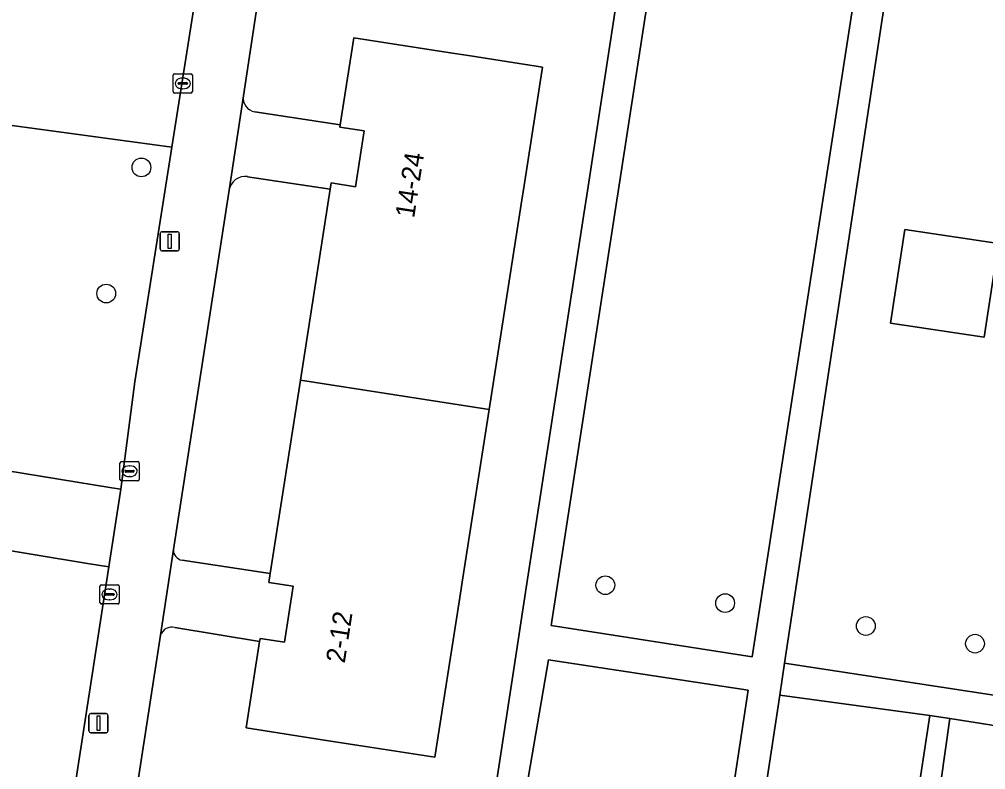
# Model space of a CAD drawing. Extents: x 161084 to 161928, y 385354 to 386522.
# Drawn here: x 161669.4 to 161719.8, y 385565.9 to 385605.1 of the extents above; entities that cross this region are included whole.
import ezdxf

# ---------------------------------------------------------------- set-up
doc = ezdxf.new("R2010")
doc.units = 0
for name, color, linetype in [('IMGEO_Boom', 7, 'Continuous'), ('IMGEO_Groenvoorziening', 7, 'Continuous'), ('IMGEO_Kolk', 7, 'Continuous'), ('IMGEO_Lichtmast', 7, 'Continuous'), ('IMGEO_Pand', 7, 'Continuous'), ('IMGEO_Pand_nummerreeks', 7, 'Continuous'), ('IMGEO_Voetpad_open', 7, 'Continuous')]:
    doc.layers.add(name, color=color, linetype=linetype)

msp = doc.modelspace()

# ---------------------------------------------------------------- linework, layer by layer
at = {"layer": 'IMGEO_Boom'}
for centre in [(161675.742, 385597.336), (161673.907, 385590.754), (161699.947, 385575.533), (161706.197, 385574.595), (161713.538, 385573.402), (161719.234, 385572.48)]:
    msp.add_circle(centre, 0.489, dxfattribs=at)
at = {"layer": 'IMGEO_Groenvoorziening'}
for points in [[(161657.824, 385601.039), (161677.325, 385598.393), (161682.306, 385629.936)], [(161682.526, 385610.747), (161681.062, 385601.073)], [(161702.191, 385606.341), (161697.119, 385573.437), (161707.611, 385571.788), (161713.072, 385607.113), (161704.883, 385608.326)], [(161676.732, 385572.916), (161675.558, 385565.255), (161684.945, 385563.794), (161686.427, 385563.563), (161693.826, 385562.411), (161695.311, 385572.063), (161695.631, 385574.145), (161695.859, 385575.628), (161698.823, 385594.901), (161698.975, 385595.889), (161700.619, 385606.575)], [(161736.552, 385603.449), (161714.658, 385606.809), (161709.299, 385571.47), (161731.363, 385568.084)], [(161681.664, 385600.231), (161686.113, 385599.559), (161686.821, 385604.108), (161691.753, 385603.34), (161692.904, 385603.16), (161696.666, 385602.574), (161695.704, 385596.399), (161695.55, 385595.411), (161693.882, 385584.702), (161692.549, 385576.144), (161692.318, 385574.661), (161691.055, 385566.552), (161686.982, 385567.187), (161685.5, 385567.417), (161681.209, 385568.086), (161681.91, 385572.586)], [(161677.325, 385598.393), (161657.824, 385601.039)], [(161663.121, 385582.422), (161674.204, 385580.619), (161674.661, 385580.545), (161675.404, 385586.149), (161677.325, 385598.393)], [(161684.036, 385586.235), (161685.589, 385596.2), (161681.285, 385596.854)], [(161680.318, 385596.144), (161677.419, 385577.388)], [(161677.87, 385576.84), (161682.463, 385576.139), (161684.036, 385586.235)], [(161674.034, 385576.484), (161672.926, 385576.668), (161664.507, 385578.062)], [(161662.849, 385544.418), (161663.304, 385544.268), (161668.139, 385543.516), (161668.928, 385543.394), (161672.366, 385565.674), (161674.034, 385576.484)], [(161681.91, 385572.586), (161677.493, 385573.331)], [(161727.809, 385567.017), (161717.914, 385568.577), (161717.223, 385563.649), (161721.705, 385562.959)]]:
    msp.add_lwpolyline(points, dxfattribs=at)
for points in [[(161719.717, 385588.484), (161720.467, 385593.373), (161715.569, 385594.099), (161714.819, 385589.209)], [(161719.717, 385588.484), (161714.819, 385589.209), (161715.569, 385594.099), (161720.467, 385593.373)], [(161707.395, 385570.046), (161696.989, 385571.64), (161695.367, 385562.217), (161705.954, 385560.553)], [(161708.692, 385535.916), (161707.425, 385536.11), (161709.051, 385546.696), (161710.63, 385556.976), (161711.897, 385556.782), (161712.382, 385559.945), (161711.116, 385560.139), (161711.784, 385564.487), (161716.127, 385563.818), (161716.872, 385568.738), (161709.056, 385569.786), (161707.615, 385560.292), (161711.058, 385559.763), (161710.876, 385558.577), (161707.433, 385559.106), (161707.374, 385558.705), (161702.137, 385524.559), (161705.558, 385523.963), (161706.317, 385528.904), (161706.975, 385533.185), (161708.242, 385532.991)]]:
    msp.add_lwpolyline(points, close=True, dxfattribs=at)
for centre, radius, start, end in [((161681.802, 385600.966), 0.748, 171.7862, 259.3406), ((161681.158, 385596.014), 0.85, 81.3757, 171.1987), ((161677.926, 385577.345), 0.508, 175.1802, 263.728), ((161677.344, 385572.699), 0.649, 76.7282, 160.4822)]:
    msp.add_arc(centre, radius, start, end, dxfattribs=at)
at = {"layer": 'IMGEO_Kolk'}
for p, q in [((161677.4, 385601.294), (161677.4, 385602.146)), ((161677.475, 385602.22), (161678.327, 385602.22)), ((161677.888, 385602), (161677.913, 385602)), ((161678.401, 385602.146), (161678.401, 385601.294)), ((161677.659, 385601.714), (161677.659, 385601.726)), ((161678.097, 385601.677), (161677.699, 385601.677)), ((161677.702, 385601.763), (161678.1, 385601.763)), ((161677.911, 385601.44), (161677.886, 385601.44)), ((161678.143, 385601.726), (161678.143, 385601.714)), ((161678.327, 385601.22), (161677.475, 385601.22)), ((161674.623, 385581.055), (161674.623, 385581.907)), ((161674.698, 385581.981), (161675.55, 385581.981)), ((161675.111, 385581.761), (161675.136, 385581.761)), ((161675.624, 385581.907), (161675.624, 385581.055)), ((161674.882, 385581.475), (161674.882, 385581.487)), ((161675.32, 385581.438), (161674.922, 385581.438)), ((161674.925, 385581.524), (161675.323, 385581.524)), ((161675.134, 385581.201), (161675.109, 385581.201)), ((161675.366, 385581.487), (161675.366, 385581.475)), ((161675.55, 385580.981), (161674.698, 385580.981)), ((161673.579, 385574.625), (161673.579, 385575.477)), ((161673.654, 385575.551), (161674.506, 385575.551)), ((161673.838, 385575.045), (161673.838, 385575.057)), ((161673.881, 385575.094), (161674.279, 385575.094)), ((161674.067, 385575.331), (161674.092, 385575.331)), ((161674.322, 385575.057), (161674.322, 385575.045)), ((161674.58, 385575.477), (161674.58, 385574.625)), ((161674.506, 385574.551), (161673.654, 385574.551)), ((161674.276, 385575.008), (161673.878, 385575.008)), ((161674.09, 385574.771), (161674.065, 385574.771))]:
    msp.add_line(p, q, dxfattribs=at)
for points in [[(161677.4, 385601.294), (161677.4, 385602.146)], [(161677.475, 385602.22), (161678.327, 385602.22)], [(161678.401, 385602.146), (161678.401, 385601.294)], [(161678.327, 385601.22), (161677.475, 385601.22)], [(161674.623, 385581.055), (161674.623, 385581.907)], [(161674.698, 385581.981), (161675.55, 385581.981)], [(161675.624, 385581.907), (161675.624, 385581.055)], [(161675.55, 385580.981), (161674.698, 385580.981)], [(161673.579, 385574.625), (161673.579, 385575.477)], [(161673.654, 385575.551), (161674.506, 385575.551)], [(161674.58, 385575.477), (161674.58, 385574.625)], [(161674.506, 385574.551), (161673.654, 385574.551)]]:
    msp.add_lwpolyline(points, dxfattribs=at)
for centre, radius, start, end in [((161677.477, 385602.144), 0.0765, 91.552, 178.448), ((161677.477, 385602.144), 0.0765, 91.552, 178.448), ((161678.325, 385602.144), 0.0765, 1.552, 88.448), ((161678.325, 385602.144), 0.0765, 1.552, 88.448), ((161677.477, 385601.296), 0.0765, 181.552, 268.448), ((161677.477, 385601.296), 0.0765, 181.552, 268.448), ((161677.699, 385601.723), 0.0403, 85.8775, 175.7526), ((161677.696, 385601.713), 0.0366, 178.938, 274.7102), ((161678.1, 385601.72), 0.043, 264.8664, 352.4533), ((161678.104, 385601.725), 0.0386, 1.7309, 96.639), ((161678.325, 385601.296), 0.0765, 271.552, 358.448), ((161678.325, 385601.296), 0.0765, 271.552, 358.448), ((161674.7, 385581.905), 0.0765, 91.552, 178.448), ((161674.7, 385581.905), 0.0765, 91.552, 178.448), ((161675.548, 385581.905), 0.0765, 1.552, 88.448), ((161675.548, 385581.905), 0.0765, 1.552, 88.448), ((161674.922, 385581.484), 0.0403, 85.8775, 175.7526), ((161674.919, 385581.474), 0.0366, 178.938, 274.7102), ((161675.323, 385581.481), 0.043, 264.8664, 352.4533), ((161675.327, 385581.486), 0.0386, 1.7309, 96.639), ((161674.7, 385581.057), 0.0765, 181.552, 268.448), ((161674.7, 385581.057), 0.0765, 181.552, 268.448), ((161675.548, 385581.057), 0.0765, 271.552, 358.448), ((161675.548, 385581.057), 0.0765, 271.552, 358.448), ((161673.656, 385575.475), 0.0765, 91.552, 178.448), ((161673.656, 385575.475), 0.0765, 91.552, 178.448), ((161673.878, 385575.054), 0.0403, 85.8775, 175.7526), ((161674.283, 385575.056), 0.0386, 1.7309, 96.639), ((161674.504, 385575.475), 0.0765, 1.552, 88.448), ((161674.504, 385575.475), 0.0765, 1.552, 88.448), ((161673.656, 385574.627), 0.0765, 181.552, 268.448), ((161673.656, 385574.627), 0.0765, 181.552, 268.448), ((161673.875, 385575.044), 0.0366, 178.938, 274.7102), ((161674.279, 385575.051), 0.043, 264.8664, 352.4533), ((161674.504, 385574.627), 0.0765, 271.552, 358.448), ((161674.504, 385574.627), 0.0765, 271.552, 358.448)]:
    msp.add_arc(centre, radius, start, end, dxfattribs=at)
for centre, major_axis, ratio, start_param, end_param in [((161677.887, 385601.72), (-0.387, 0.002), 0.722429, 4.712389, 7.853982), ((161677.912, 385601.72), (-0.39, 0.002), 0.717154, 1.570796, 4.712389), ((161675.11, 385581.481), (-0.387, 0.002), 0.722429, 4.712389, 7.853982), ((161675.135, 385581.481), (-0.39, 0.002), 0.717154, 1.570796, 4.712389), ((161674.066, 385575.051), (-0.387, 0.002), 0.722429, 4.712389, 7.853982), ((161674.091, 385575.051), (-0.39, 0.002), 0.717154, 1.570796, 4.712389)]:
    msp.add_ellipse(centre, major_axis=major_axis, ratio=ratio, start_param=start_param, end_param=end_param, dxfattribs=at)
at = {"layer": 'IMGEO_Lichtmast'}
for p, q in [((161676.725, 385593.08), (161676.725, 385593.88)), ((161676.725, 385593.88), (161676.725, 385593.08)), ((161676.825, 385593.98), (161677.615, 385593.98)), ((161677.615, 385593.98), (161676.825, 385593.98)), ((161677.715, 385593.88), (161677.715, 385593.08)), ((161677.715, 385593.08), (161677.715, 385593.88)), ((161677.615, 385592.98), (161676.825, 385592.98)), ((161676.825, 385592.98), (161677.615, 385592.98)), ((161673.006, 385567.931), (161673.006, 385568.731)), ((161673.006, 385568.731), (161673.006, 385567.931)), ((161673.106, 385568.831), (161673.896, 385568.831)), ((161673.896, 385568.831), (161673.106, 385568.831)), ((161673.996, 385568.731), (161673.996, 385567.931)), ((161673.996, 385567.931), (161673.996, 385568.731)), ((161673.896, 385567.831), (161673.106, 385567.831)), ((161673.106, 385567.831), (161673.896, 385567.831))]:
    msp.add_line(p, q, dxfattribs=at)
for points in [[(161677.145, 385593.855), (161677.295, 385593.855), (161677.295, 385593.105), (161677.145, 385593.105), (161677.145, 385593.855)], [(161673.426, 385568.706), (161673.576, 385568.706), (161673.576, 385567.956), (161673.426, 385567.956), (161673.426, 385568.706)]]:
    msp.add_lwpolyline(points, dxfattribs=at)
for centre, start, end in [((161676.825, 385593.88), 90, 180), ((161676.825, 385593.88), 90, 180), ((161677.615, 385593.88), 0, 90), ((161677.615, 385593.88), 360, 90), ((161676.825, 385593.08), 180, 270), ((161676.825, 385593.08), 180, 270), ((161677.615, 385593.08), 270, 0), ((161677.615, 385593.08), 270, 0), ((161673.106, 385568.731), 90, 180), ((161673.106, 385568.731), 90, 180), ((161673.896, 385568.731), 0, 90), ((161673.896, 385568.731), 360, 90), ((161673.106, 385567.931), 180, 270), ((161673.106, 385567.931), 180, 270), ((161673.896, 385567.931), 270, 0), ((161673.896, 385567.931), 270, 0)]:
    msp.add_arc(centre, 0.1, start, end, dxfattribs=at)
at = {"layer": 'IMGEO_Pand'}
for points in [[(161695.55, 385595.411), (161695.704, 385596.399), (161696.666, 385602.574), (161692.904, 385603.16), (161691.753, 385603.34), (161686.821, 385604.108), (161686.113, 385599.559), (161686.095, 385599.445), (161687.363, 385599.248), (161686.908, 385596.327), (161685.64, 385596.524), (161685.589, 385596.2), (161684.036, 385586.235), (161693.882, 385584.702)], [(161693.882, 385584.702), (161684.036, 385586.235), (161682.463, 385576.139), (161682.392, 385575.681), (161683.661, 385575.484), (161683.204, 385572.553), (161681.936, 385572.75), (161681.91, 385572.586), (161681.209, 385568.086), (161685.5, 385567.417), (161686.982, 385567.187), (161691.055, 385566.552), (161692.318, 385574.661), (161692.549, 385576.144)]]:
    msp.add_lwpolyline(points, close=True, dxfattribs=at)
at = {"layer": 'IMGEO_Voetpad_open'}
for points in [[(161682.306, 385629.936), (161677.325, 385598.393), (161675.404, 385586.149), (161674.661, 385580.545), (161674.034, 385576.484), (161672.366, 385565.674), (161668.928, 385543.394), (161668.239, 385538.924), (161668.116, 385538.133), (161667.803, 385536.052), (161663.625, 385508.283), (161661.817, 385496.26), (161658.19, 385472.711), (161656.38, 385460.922), (161656.38, 385460.904), (161655.699, 385456.628), (161655.683, 385456.575), (161655.028, 385452.288)], [(161675.205, 385563.675), (161675.558, 385565.255), (161676.732, 385572.916), (161677.419, 385577.388), (161680.318, 385596.144), (161681.062, 385601.073), (161682.526, 385610.747), (161683.06, 385614.032), (161684.287, 385621.684), (161684.764, 385624.801), (161685.325, 385629.197)], [(161704.883, 385608.326), (161704.848, 385608.336), (161700.995, 385608.885), (161700.619, 385606.575), (161698.975, 385595.889), (161698.823, 385594.901), (161695.859, 385575.628), (161695.631, 385574.145), (161695.311, 385572.063), (161693.826, 385562.411), (161693.582, 385560.823), (161696.695, 385560.34), (161705.534, 385558.969), (161707.374, 385558.705), (161707.433, 385559.106), (161707.615, 385560.292), (161709.056, 385569.786)], [(161709.056, 385569.786), (161709.299, 385571.47), (161714.658, 385606.809), (161713.072, 385607.113), (161707.611, 385571.788), (161697.119, 385573.437), (161702.191, 385606.341)], [(161681.062, 385601.073), (161680.318, 385596.144)], [(161681.285, 385596.854), (161685.589, 385596.2), (161685.64, 385596.524), (161686.908, 385596.327), (161687.363, 385599.248), (161686.095, 385599.445), (161686.113, 385599.559), (161681.664, 385600.231)], [(161677.419, 385577.388), (161676.732, 385572.916)], [(161682.463, 385576.139), (161677.87, 385576.84)], [(161677.493, 385573.331), (161681.91, 385572.586), (161681.936, 385572.75), (161683.204, 385572.553), (161683.661, 385575.484), (161682.392, 385575.681), (161682.463, 385576.139)], [(161731.363, 385568.084), (161709.299, 385571.47), (161709.056, 385569.786), (161716.872, 385568.738), (161717.914, 385568.577), (161727.809, 385567.017)]]:
    msp.add_lwpolyline(points, dxfattribs=at)
for points in [[(161674.661, 385580.545), (161674.204, 385580.619), (161663.121, 385582.422), (161664.507, 385578.062), (161672.926, 385576.668), (161674.034, 385576.484)], [(161707.395, 385570.046), (161705.954, 385560.553), (161695.367, 385562.217), (161696.989, 385571.64)], [(161716.872, 385568.738), (161716.127, 385563.818), (161717.223, 385563.649), (161717.914, 385568.577)]]:
    msp.add_lwpolyline(points, close=True, dxfattribs=at)
for centre, radius, start, end in [((161681.802, 385600.966), 0.748, 171.7862, 259.3406), ((161681.158, 385596.014), 0.85, 81.3757, 171.1987), ((161677.926, 385577.345), 0.508, 175.1802, 263.728), ((161677.344, 385572.699), 0.649, 76.7282, 160.4822)]:
    msp.add_arc(centre, radius, start, end, dxfattribs=at)

# ---------------------------------------------------------------- texts
at = {"layer": 'IMGEO_Pand_nummerreeks'}
for s, rotation, p in [('14-24', 81.148, (161689.968, 385594.66)), ('2-12', 81.1366, (161686.349, 385571.43))]:
    msp.add_text(s, height=1, rotation=rotation, dxfattribs=at).set_placement(p)

doc.saveas('drawing.dxf')
